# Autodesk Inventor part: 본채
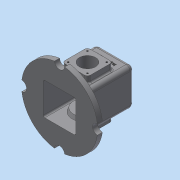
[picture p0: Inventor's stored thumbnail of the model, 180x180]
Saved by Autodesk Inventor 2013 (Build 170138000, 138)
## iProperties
Created: 2018-07
Part Number: 본채
Material: 일반
Document SubType Name: Modeling
Designer: dgall
Density: 1 g/cm^3
Author: dgall
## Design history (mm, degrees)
sketch "스케치6"
  geometry: L1 (0, 0)-(-74, 0); L2 (-74, 0)-(-74, -74); L3 (-74, -74)-(0, -74); L4 (0, -74)-(0, 0)
  constraints: 8 end point, 2 parallel, 2 perpendicular, 1 horizontal
  dimensions: "d23" = 74 distance of L2.end L3.end
extrude "돌출6" new body sketch "스케치6" distance "d25" = 110; taper "d26" = 0 deg
node "작업 평면3"
sketch "스케치7"
  geometry: L1 (74, 0)-(0, 0) reference; L2 (0, 0)-(0, 110) reference; L3 (74, 110)-(0, 110) reference; L4 (74, 0)-(74, 110) reference; L5 (-13, 55)-(87, 55); L6 (-13, 71)-(87, 71); L7 (87, 71)-(87, 80); L8 (87, 80)-(-13, 80); L9 (-13, 80)-(-13, 71); 4 further points
  constraints: 10 end point, 4 vertical alignment, 3 midpoint, 3 parallel, 2 perpendicular
  dimensions: "d27" = 55 distance between parallel lines of L1 L5; "d28" = 32 diameter of L6 L5; "d29" = 50 diameter of L8 L5; "d30" = 100 distance between parallel lines of L7 L9
revolve "회전2" sketch "스케치7" stored, may be unused: angle "d31" = 90 deg
sketch "스케치8"
  geometry: L1 (25, 25)-(25, -25); L2 (25, -25)-(-25, -25); L3 (-25, -25)-(-25, 25); L4 (-25, 25)-(25, 25); C1 r 16 at (0, 0) reference; 5 further points
  constraints: 8 end point, 2 midpoint, 1 coincident, 1 horizontal alignment, 1 vertical alignment, 10 other
extrude "돌출7" join sketch "스케치8" distance "d32" = 100; taper "d33" = 0 deg
sketch "스케치9"
  geometry: L1 (0, 0)-(74, 0) reference; L2 (0, -74)-(0, 0) reference; L3 (74, -74)-(0, -74) reference; L4 (74, 0)-(74, -74) reference; C1 r 75 at (37, -37); 2 further points
  constraints: 2 midpoint, 1 centre point, 1 horizontal alignment, 1 vertical alignment
  dimensions: "d34" = 150 diameter of C1
extrude "돌출8" join sketch "스케치9" distance "d36" = 10; taper "d37" = 0 deg
sketch "스케치10"
  geometry: A1 r 75 centre (0, 0) between (0, 75) and (-75, 0) reference; A2 r 10 centre (0, 75) between (-9.978, 74.333) and (9.978, 74.333); A3 r 10 centre (-75, 0) between (-74.333, -9.978) and (-74.333, 9.978)
  constraints: 10 point on circle, 2 centre point, 1 equal radius, 1 horizontal alignment, 1 vertical alignment
  dimensions: "d38" = 10 radius of A2
extrude "돌출9" cut sketch "스케치10" distance "d40" = 10; taper "d41" = 0 deg
extrude "돌출10" cut sketch "스케치10" distance "d42" = 10; taper "d43" = 0 deg
node "작업 평면4"
sketch "스케치11"
  geometry: L1 (46.978, 0)-(27.022, 0) reference; L2 (-37.333, 0)-(27.022, 0) reference; L3 (-37.333, 0)-(-37.333, 0) reference; L4 (27.022, 0)-(-37.333, 0) reference; L5 (27.022, 0)-(46.978, 0) reference; L6 (111.333, 0)-(46.978, 0) reference; L7 (111.333, 0)-(111.333, 0) reference; L8 (46.978, 0)-(111.333, 0) reference; L9 (5, 105)-(69, 105); L10 (69, 105)-(69, 0); L11 (69, 0)-(5, 0); L12 (5, 0)-(5, 105); L13 (74, 110)-(0, 110) reference; 3 further points
  constraints: 8 end point, 3 midpoint, 2 parallel, 1 coincident, 1 horizontal, 1 perpendicular
  dimensions: "d44" = 64 distance between parallel lines of L10 L12; "d47" = 5 distance between parallel lines of L9 L13
extrude "돌출11" cut sketch "스케치11" stored distance "d48" = 64; taper "d49" = 0 deg
sketch "스케치12"
  geometry: L1 (5, 0)-(5, 105) reference; L2 (5, 75)-(12, 72.452); L3 (12, 72.452)-(12, 50); L4 (12, 50)-(5, 50); L5 (69, 0)-(5, 0) reference; 1 further point
  constraints: 6 end point, 2 point on line, 1 parallel, 1 perpendicular
  dimensions: "d50" = 50 diameter of L2.start L4; "d52" = 50 distance from line of L5 L4.end; "d54" = 110 deg angle of L3 L2; "d55" = 7 distance between parallel lines of L1 L3
revolve "회전3" sketch "스케치12" stored, may be unused: angle "d56" = 90 deg
sketch "스케치13"
  geometry: C1 r 16 at (25, 25) reference; C2 r 16 at (25, 25); 1 further point
  constraints: 1 centre point, 1 coincident, 1 concentric
extrude "돌출12" cut sketch "스케치13" stored distance "d57" = 64; taper "d58" = 0 deg
node "작업 평면5"
sketch "스케치14"
  geometry: L1 (17, 57)-(57, 57); L2 (57, 57)-(57, 17); L3 (57, 17)-(17, 17); L4 (17, 17)-(17, 57); L5 (0, 0)-(74, 0) reference; L6 (74, 0)-(74, 74) reference; L7 (74, 74)-(0, 74) reference; L8 (0, 74)-(0, 0) reference; 5 further points
  constraints: 8 end point, 4 midpoint, 2 parallel, 2 perpendicular, 1 horizontal, 1 horizontal alignment, 1 vertical alignment
  dimensions: "d60" = 40 distance of L1.end L2.end
  node "투영된 루프4"
extrude "돌출13" join sketch "스케치14" stored distance "d62" = 64; taper "d63" = 0 deg
extrude "돌출14" cut sketch "스케치14" distance "d64" = 3; taper "d65" = 0 deg
sketch "스케치15"
  geometry: L1 (17, 57)-(57, 57) reference; L2 (17, 17)-(17, 57) reference; C1 r 10.5 at (37, 37); C2 r 14 at (37, 37); C3 r 17.5 at (37, 37); 3 further points
  constraints: 3 centre point, 2 coincident, 2 midpoint, 1 horizontal alignment, 1 vertical alignment
  dimensions: "d66" = 35 diameter of C3; "d68" = 28 diameter of C2; "d69" = 21 diameter of C1
extrude "돌출15" join sketch "스케치15" distance "d70" = 3; taper "d71" = 0 deg
extrude "돌출16" cut sketch "스케치15" stored distance "d72" = 3; taper "d73" = 0 deg
extrude "돌출17" cut sketch "스케치15" distance "d74" = 1; taper "d75" = 0 deg
fillet "모깎기1" dims "d76" = 6
fillet "모깎기2" dims "d77" = 3
fillet "모깎기3" dims "d78" = 8
sketch "스케치16"
  geometry: A1 r 6 centre (0, -6) between (0, 0) and (-6, -6) reference; 2 further points
  constraints: 1 coincident
hole "구멍1" sketch "스케치16" at (0, -6) diameter "d79" = 3.242; stored, may be unused: countersink angle "d83" = 90 deg, drill point angle "d85" = 118 deg; dims "d80" = 8, "d81" = 4, "d82" = 2, "d84" = 10
fillet "모깎기4" dims "d89" = 3
fillet "모깎기5" dims "d90" = 3
node "작업 평면6"
sketch "스케치17"
  geometry: L1 (10, -75)-(48, -75) reference; L2 (1, -28)-(1, -66) reference; L3 (48, -19)-(10, -19) reference; L4 (57, -66)-(57, -28) reference; L5 (58, -89)-(0, -89) reference; L6 (58, 0)-(58, -89) reference; L7 (0, 0)-(58, 0) reference; L8 (0, -89)-(0, 0) reference; L9 (46.5, 18)-(11.5, 18) reference; A1 r 9 centre (48, -66) between (48, -75) and (57, -66) reference; A2 r 9 centre (10, -66) between (1, -66) and (10, -75) reference; A3 r 9 centre (10, -28) between (10, -19) and (1, -28) reference; A4 r 9 centre (48, -28) between (57, -28) and (48, -19) reference; 3 further points
  constraints: 1 midpoint, 1 vertical alignment, 1 other
  dimensions: "d92" = 30 distance from line of point (29, -12) L9
feature "엠보싱1" sketch "스케치17" dims "d27" = 55, "d28" = 32, "d29" = 50, "d30" = 100, "d93" = 0.5, "d94" = 0
node "솔리드2"
mirror "대칭3"
mirror "대칭4"
mirror "대칭5"
pattern_circular "원형 패턴1" dims angle "d87" = 360 deg
mirror "대칭6"
node "투영된 루프2"
node "투영된 루프3"
node "투영된 루프5"
other parameters: "d91" = 15
